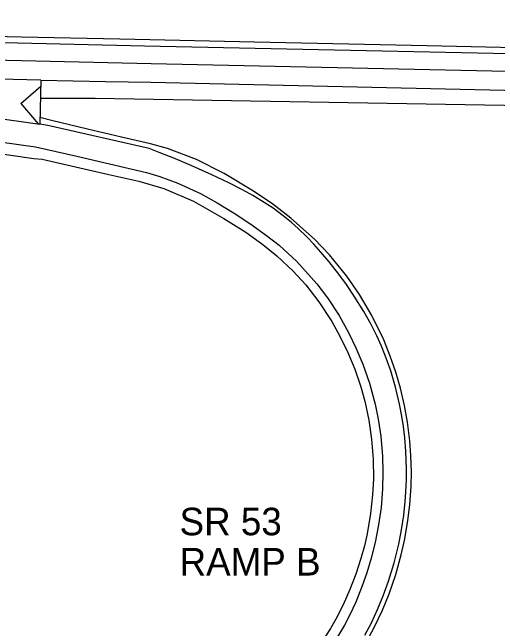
# Model space of a CAD drawing. Extents: x 1855721 to 1876784, y 662259 to 674089.
# Drawn here: x 1870216.1 to 1870533.7, y 669857.2 to 670260.1 of the extents above; entities that cross this region are included whole.
import ezdxf

# ---------------------------------------------------------------- set-up
doc = ezdxf.new("R2010")
doc.units = 0
for name, color, linetype in [('_CIVIL_CONSTRUCTION', 7, 'Continuous'), ('GE_X_Alignment_100_Bearings', 7, 'Continuous'), ('GE_X_Alignment_100_Cardinal_Points', 7, 'Continuous'), ('GE_X_Alignment_100_Curve_Data', 7, 'Continuous'), ('SC_Scratch1', 7, 'Continuous')]:
    doc.layers.add(name, color=color, linetype=linetype)

msp = doc.modelspace()

# ---------------------------------------------------------------- linework, layer by layer
at = {"layer": '_CIVIL_CONSTRUCTION'}
msp.add_line((1870234.8, 670215.72), (1870234.04, 670187.27), dxfattribs=at)
for points in [[(1870234.8, 670215.72), (1870277.14, 670214.96), (1870306.82, 670214.43), (1870547.81, 670209.13), (1870575.11, 670208.54), (1870809.46, 670203.68), (1870850.75, 670202.82), (1871050.46, 670198.65), (1871080.01, 670198.03)], [(1870195.29, 670177.22), (1870231.27, 670172.14), (1870258.28, 670166.1), (1870279.71, 670161.09), (1870303.84, 670155.42), (1870312.59, 670152.86), (1870324.41, 670148.49), (1870339.18, 670141.62), (1870350.18, 670135.61), (1870361.3, 670128.91), (1870372.27, 670121.73), (1870382.54, 670114.31), (1870390.65, 670107.85), (1870402.32, 670097.24), (1870415.4, 670082.72), (1870422.43, 670073.39), (1870429.95, 670061.85), (1870436.31, 670050.45), (1870441, 670040.74), (1870445.41, 670030.19), (1870449.77, 670017.67), (1870453.53, 670003.93), (1870455.55, 669994.2), (1870457.25, 669982.98), (1870458.4, 669969.68), (1870458.66, 669959.47), (1870458.36, 669948.42), (1870457.37, 669936.5), (1870455.78, 669925.13), (1870453.52, 669913.53), (1870450.95, 669903.22), (1870448.11, 669893.75), (1870445.09, 669885.13), (1870440.8, 669874.59), (1870436.91, 669866.29), (1870433.39, 669859.53), (1870426.98, 669848.67)]]:
    msp.add_lwpolyline(points, dxfattribs=at)
at = {"layer": 'GE_X_Alignment_100_Bearings'}
msp.add_lwpolyline([(1869304.01, 670248.74), (1869402.4, 670246.63), (1869701.27, 670239.83), (1869838.6, 670236.8), (1869901.39, 670235.7), (1870061.29, 670232.32), (1870306.95, 670226.64), (1870570.41, 670220.93), (1870827.85, 670215.6), (1871080.56, 670210.16), (1871438.65, 670202.48), (1871763.97, 670195.25), (1872009.16, 670190.02), (1872201.36, 670186.27), (1872386.22, 670182.41), (1872671.76, 670176.66)], dxfattribs=at)
at = {"layer": 'GE_X_Alignment_100_Cardinal_Points'}
for q in [(1870234.7, 670211.83), (1870233.02, 670187.23)]:
    msp.add_line((1870221.57, 670200.53), q, dxfattribs=at)
msp.add_lwpolyline([(1870234.8, 670215.72), (1869934.44, 670222.99), (1870056.98, 670210.49), (1870133.88, 670201.18), (1870234.04, 670187.11)], dxfattribs=at)
at = {"layer": 'GE_X_Alignment_100_Curve_Data'}
for points in [[(1869312.19, 670260.13), (1869356.66, 670259.09), (1869411.58, 670257.82), (1869662.96, 670252.5), (1869704.1, 670251.62), (1869832.77, 670248.6), (1869881.61, 670247.5), (1869917.95, 670246.72), (1870016.19, 670244.73), (1870072.19, 670243.57), (1870302.52, 670238.15), (1870374.92, 670236.63), (1870561.95, 670232.73), (1870645.26, 670231.01), (1870824.17, 670227.32), (1870930.78, 670225.03), (1871078.75, 670221.85), (1871163.65, 670220.03)], [(1870263.24, 670180.67), (1870239.38, 670186.06), (1870234.04, 670187.11)], [(1870446.85, 669852.96), (1870451.07, 669861.09), (1870455.08, 669869.66), (1870458.83, 669878.65), (1870462.29, 669888.15), (1870466.02, 669900.25), (1870469.03, 669912.46), (1870470.83, 669921.76), (1870472.28, 669931.5), (1870473.23, 669940.43), (1870473.67, 669946.63), (1870473.99, 669954.45), (1870474.04, 669961.57), (1870473.64, 669973.2), (1870472.93, 669982), (1870472.07, 669989.29), (1870471.03, 669996.14), (1870469.55, 670004), (1870466.95, 670014.99), (1870463.78, 670025.69), (1870460.16, 670035.78), (1870457.7, 670041.8), (1870454.61, 670048.61), (1870450.9, 670056), (1870446.15, 670064.5), (1870439.88, 670074.61), (1870434.77, 670082.09), (1870429.69, 670089.03), (1870423.43, 670096.97), (1870418, 670103.39), (1870413.47, 670108.46), (1870408.74, 670113.44), (1870403.19, 670118.83), (1870398.78, 670122.75), (1870393.4, 670127.15), (1870386.74, 670132.05), (1870379.19, 670137), (1870373.6, 670140.35), (1870366.76, 670144.12), (1870357.7, 670148.73), (1870346.6, 670153.98), (1870333.64, 670159.72), (1870322.78, 670164.3), (1870312.14, 670168.59), (1870305.6, 670171.08), (1870263.24, 670180.67)]]:
    msp.add_lwpolyline(points, dxfattribs=at)
at = {"layer": 'SC_Scratch1'}
for points in [[(1869971.04, 670249.82), (1870035.68, 670248.42), (1870088.03, 670247.25), (1870147.03, 670245.9), (1870222.18, 670244.18), (1870286.43, 670242.7), (1870374.51, 670240.81), (1870487.6, 670238.42), (1870564.28, 670236.8), (1870653.78, 670234.91), (1870763.31, 670232.61), (1870838.63, 670231.02), (1870939.83, 670228.88), (1870999.36, 670227.62), (1871057.84, 670226.39), (1871116.3, 670225.15)], [(1870234.49, 670203.93), (1870270.24, 670204.08), (1870550.58, 670199.25), (1870734.97, 670195.37), (1870837.14, 670193.22), (1870942.52, 670191.05), (1871014.97, 670189.55), (1871071.82, 670188.37), (1871079.87, 670188.21)], [(1870448.11, 669849.06), (1870453.15, 669858.48), (1870458.24, 669869.28), (1870462.63, 669880.01), (1870467.01, 669892.67), (1870470.57, 669905.35), (1870472.73, 669914.89), (1870474.96, 669927.71), (1870476.22, 669938.33), (1870477.03, 669950.24), (1870477.22, 669959.65), (1870476.93, 669970.45), (1870476.24, 669979.99), (1870474.7, 669992.27), (1870472.75, 670003.11), (1870470.08, 670014.45), (1870467.06, 670024.84), (1870463.38, 670035.42), (1870459.12, 670045.92), (1870451.32, 670061.91), (1870443.26, 670075.61), (1870434.94, 670087.66), (1870423.69, 670101.52), (1870413.8, 670111.9), (1870398.47, 670125.54), (1870386.5, 670134.69), (1870373.9, 670143.28), (1870354.71, 670154.81), (1870336.57, 670163.83), (1870317.58, 670171), (1870306.49, 670174.05), (1870287.6, 670178.53), (1870265.23, 670183.82), (1870241.69, 670189.4), (1870234.15, 670191.28)], [(1870196.77, 670169.28), (1870230.19, 670164.54), (1870235.67, 670164.03), (1870279.37, 670154.11), (1870298.97, 670149.66), (1870315.15, 670144.93), (1870334.56, 670136.59), (1870354.61, 670125.45), (1870368.89, 670116.34), (1870380.14, 670108.27), (1870389.23, 670100.93), (1870399.97, 670090.94), (1870408.14, 670081.99), (1870416.78, 670070.92), (1870425.18, 670058.09), (1870430.51, 670048.52), (1870435.73, 670037.71), (1870440.2, 670026.8), (1870444.12, 670015.3), (1870446.73, 670005.91), (1870449.42, 669993.49), (1870451.25, 669981.14), (1870452.28, 669968.03), (1870452.41, 669955.02), (1870451.91, 669944.79), (1870450.59, 669932.49), (1870448.31, 669919.22), (1870446.52, 669911.39), (1870444.26, 669903.07), (1870440.92, 669892.74), (1870437.06, 669882.71), (1870432.57, 669872.69), (1870427.78, 669863.39), (1870424.31, 669857.33), (1870417.82, 669847.19)]]:
    msp.add_lwpolyline(points, dxfattribs=at)

# ---------------------------------------------------------------- texts
for s, p in [('SR 53', (1870325.54, 669918.25)), ('RAMP B', (1870325.54, 669891.92))]:
    msp.add_text(s, height=18, dxfattribs=at).set_placement(p)

doc.saveas('drawing.dxf')
